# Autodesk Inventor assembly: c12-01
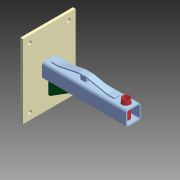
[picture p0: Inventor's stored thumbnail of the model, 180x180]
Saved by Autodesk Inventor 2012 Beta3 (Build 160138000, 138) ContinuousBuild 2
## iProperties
Created: 2011-01
Part Number: c12-01
Document SubType Name: Assembly
Designer: Beta-8540w
_SolveAssemblyDoc: Frame Generator Solve Assembly
_Version: 15.0.0
Author: Beta-8540w
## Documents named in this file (5)
- C:\Inventor 2012 Essentials\Assemblies\Chapter 12\c12-01.iam
- C:\Inventor 2012 Essentials\Parts\Chapter 12\c12-01.ipt
- C:\Inventor 2012 Essentials\Parts\Chapter 12\c12-02.ipt
- C:\Inventor 2012 Essentials\Assemblies\Chapter 12\Frame\Frame c12-01.iam
- C:\Inventor 2012 Essentials\Parts\Chapter 12\c12-03.ipt
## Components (4 placed, 4 different names)
1. c12-01:1 — Mate:2
2. c12-02:1 — Flush:1
3. Frame c12-01:1 [sub-assembly] — Mate:3
4. c12-03:1 — Mate:1, Mate:2, Mate:3
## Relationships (4: Mate 3, Flush 1)
- Flush:1: c12-02:1
- Mate:1: c12-03:1
- Mate:2: c12-01:1 ↔ c12-03:1
- Mate:3: Frame c12-01:1 ↔ c12-03:1
